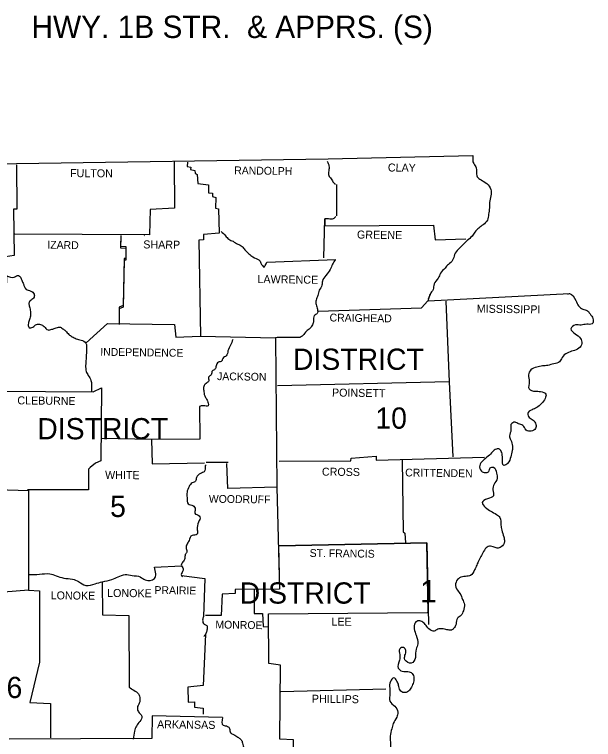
# Model space of a CAD drawing. Extents: x 155 to 3386, y 68 to 2138.
# Drawn here: x 2999.8 to 3303.9, y 1654.1 to 2035 of the extents above; entities that cross this region are included whole.
import ezdxf

# ---------------------------------------------------------------- set-up
doc = ezdxf.new("R2010")
doc.units = 0
for name, color, linetype in [('1', 7, 'Continuous'), ('2', 7, 'Continuous'), ('3', 7, 'Continuous'), ('R_Border', 7, 'Continuous'), ('S_MISC_BOUNDARY', 7, 'Continuous')]:
    doc.layers.add(name, color=color, linetype=linetype)

msp = doc.modelspace()

# ---------------------------------------------------------------- linework, layer by layer
at = {"layer": '1'}
for p, q in [((3216.98, 1884.51), (3218.15, 1888.13)), ((3217.27, 1885.68), (3218.45, 1888.52)), ((3100.35, 1799.78), (3112, 1799.78))]:
    msp.add_line(p, q, dxfattribs=at)
for points in [[(2703.71, 1956.42), (2861.92, 1956.32), (3000.75, 1956.61), (3164.54, 1959.16), (3240.46, 1960.92)], [(3083.62, 1957.49), (3083.82, 1933.23), (3071.1, 1932.55), (3070.71, 1919.24), (2999.97, 1919.63)], [(3090.67, 1957.4), (3090.37, 1955.05), (3092.33, 1954.76), (3092.23, 1953.58), (3094.48, 1953.09), (3094.68, 1951.53), (3095.75, 1950.84), (3096.05, 1946.15), (3101.63, 1945.56), (3101.63, 1941.35), (3103.68, 1941.06), (3103.68, 1939.39), (3105.44, 1938.9), (3105.34, 1933.23), (3106.91, 1932.94), (3107.3, 1920.12), (3098.98, 1919.34), (3099.08, 1916.6), (3096.54, 1916.5), (3097.42, 1866.01), (3136.85, 1865.13), (3137.53, 1786.66), (3111.8, 1785.98), (3111.31, 1799.19)], [(3000.75, 1956.03), (3000.95, 1932.74), (2999.28, 1932.64), (2999.58, 1908.28), (2992.73, 1907.3), (2993.32, 1900.75), (2995.66, 1897.71), (2995.47, 1889.98), (2982.16, 1889.5), (2981.67, 1877.56), (2969.54, 1877.17), (2968.95, 1862.69), (2969.64, 1861.51), (2969.93, 1838.42), (2990.87, 1837.05), (2990.58, 1785.49), (3007.21, 1785), (3007.21, 1732.56), (2994.1, 1731.58), (2993.12, 1720.04), (2971.11, 1719.94)], [(3168.84, 1945.66), (3168.84, 1929.12)], [(3162.19, 1907.11), (3162.68, 1927.56), (3162.68, 1923.94), (3219.91, 1924.23), (3220.7, 1916.6), (3236.84, 1917.18)], [(3055.64, 1918.95), (3055.44, 1913.27), (3058.18, 1913.07), (3058.28, 1906.81), (3057.3, 1906.81), (3056.91, 1882.16), (3054.66, 1881.18), (3054.66, 1872.96)], [(3055.64, 1918.06), (3055.44, 1912.39), (3058.18, 1912.19), (3058.28, 1905.93), (3057.3, 1905.93), (3056.91, 1881.28), (3054.66, 1880.3), (3054.66, 1872.08)], [(3067.87, 1918.75), (3067.97, 1918.85)], [(3132.25, 1904.95), (3168.55, 1906.23)], [(3216.98, 1884.51), (3291.24, 1888.32)], [(3159.25, 1879.12), (3213.55, 1880.89), (3216.78, 1884.6)], [(3226.37, 1884.41), (3228.04, 1842.04), (3229.99, 1802.61)], [(3037.44, 1862.49), (3048.6, 1872.57), (3083.82, 1872.08), (3084.5, 1865.52), (3097.32, 1866.01)], [(3149.67, 1865.33), (3137.73, 1865.33), (3136.85, 1865.13)], [(3228.04, 1842.04), (3137.92, 1839.99)], [(2990.87, 1837.05), (3041.16, 1836.76), (3045.46, 1838.81), (3045.17, 1800.56), (3042.24, 1799.29), (3039.59, 1797.04), (3038.71, 1796.16), (3038.62, 1785.2), (3006.62, 1785.2)], [(3096.93, 1829.03), (3097.12, 1811.81), (3071.69, 1811.71), (3045.56, 1812.2)], [(3071.69, 1811.71), (3072.08, 1798.89), (3099.57, 1799.38)], [(3138.71, 1800.36), (3176.47, 1800.56), (3176.57, 1801.93), (3189.68, 1802.91), (3189.68, 1800.85), (3246.63, 1802.42)], [(3100.35, 1798.11), (3099.86, 1798.01)], [(3203.38, 1800.85), (3203.87, 1763.18), (3204.75, 1762.6), (3205.04, 1757.51)], [(3137.53, 1786.66), (3139, 1733.05), (3115.71, 1732.95), (3115.62, 1730.8), (3108.87, 1730.41), (3108.28, 1719.25), (3100.06, 1719.25)], [(3138.71, 1755.85), (3216.39, 1757.41)], [(3216.39, 1757.41), (3217.18, 1714.56)], [(3073.25, 1744.69), (3087.44, 1745.38)], [(3045.86, 1737.06), (3046.05, 1719.55), (3059.85, 1719.25), (3059.95, 1681.68)], [(3087.44, 1740.29), (3099.67, 1738.72), (3098.98, 1718.76)], [(3007.21, 1732.56), (3012.88, 1732.17), (3012.98, 1694.79), (3007.89, 1673.56), (3018.75, 1673.07), (3018.66, 1655.07)], [(3125.69, 1732.46), (3125.6, 1720.33), (3130.1, 1720.33), (3130.29, 1713.58), (3133.13, 1713.28)], [(3138.71, 1633.54), (3146.34, 1634.03), (3146.24, 1653.9), (3139.1, 1654.38), (3139.49, 1693.23), (3133.33, 1694.11), (3133.13, 1720.23), (3216.59, 1720.82)], [(3100.06, 1709.37), (3098.89, 1682.56), (3090.86, 1681.68), (3091.06, 1673.76), (3094.29, 1673.85), (3094.39, 1671.11), (3098.79, 1670.63), (3098.89, 1667.4)], [(3139.69, 1679.43), (3194.87, 1680.8)], [(3109.06, 1665.64), (3072.08, 1666.61), (3071.88, 1654.58), (2997.03, 1654.29)]]:
    msp.add_lwpolyline(points, dxfattribs=at)
for points in [[(3164.05, 1957.89), (3164.93, 1955.44), (3164.83, 1952.8), (3164.83, 1950.35), (3166.1, 1948.69), (3167.37, 1946.63), (3168.35, 1945.75)], [(3240.46, 1960.92), (3240.95, 1956.61), (3242.32, 1954.36), (3242.52, 1950.25), (3244.18, 1948.49), (3247.02, 1946.73), (3249.56, 1943.89), (3250.15, 1940.57), (3249.36, 1937.14), (3249.17, 1933.33), (3248.78, 1930), (3248.19, 1926.97), (3245.84, 1924.52), (3243.59, 1922.76), (3241.54, 1920.71), (3240.07, 1918.55), (3237.53, 1916.21), (3234.98, 1913.76), (3232.93, 1911.61), (3230.87, 1908.87), (3229.89, 1905.83), (3227.64, 1903.68), (3225.88, 1901.73), (3223.53, 1899.08), (3222.36, 1896.44), (3220.11, 1893.41), (3219.62, 1890.47), (3218.15, 1888.13), (3218.06, 1887.73)], [(3168.45, 1928.83), (3167.18, 1927.56), (3164.73, 1927.56), (3162.68, 1927.56)], [(3108.38, 1921), (3110.53, 1918.75), (3112.39, 1916.89), (3114.54, 1915.81), (3117.08, 1914.35), (3119.33, 1913.17), (3120.8, 1911.31), (3122.86, 1909.26), (3124.91, 1907.6), (3128.14, 1906.03), (3129.22, 1904.37), (3130.68, 1902.31), (3132.25, 1904.95)], [(3168.25, 1906.13), (3166.79, 1903.78), (3165.61, 1901.04), (3163.26, 1897.91), (3161.5, 1894.88), (3161.21, 1892.82), (3159.84, 1890.08), (3159.06, 1887.34), (3158.18, 1884.99), (3158.18, 1882.55), (3158.86, 1880.1), (3158.67, 1877.85), (3157.2, 1876.78), (3156.81, 1873.94), (3156.22, 1871.98), (3154.95, 1870.03), (3153.09, 1868.56), (3151.13, 1866.31), (3149.67, 1865.33)], [(2995.66, 1897.71), (2999.58, 1897.03), (3001.93, 1897.91), (3003.59, 1895.37), (3004.47, 1893.41), (3005.94, 1890.57), (3008.29, 1889.69), (3010.05, 1888.13), (3010.05, 1886.46), (3008.48, 1884.9), (3007.31, 1883.33), (3007.7, 1881.47), (3008.09, 1878.93), (3008.09, 1876.48), (3007.5, 1874.23), (3007.01, 1872.18), (3007.5, 1870.42), (3009.36, 1870.71), (3011.32, 1872.18), (3013.37, 1872.18), (3015.33, 1871.1), (3017.38, 1869.24), (3019.44, 1869.63), (3021.1, 1870.12), (3023.45, 1870.81), (3025.11, 1869.93), (3026.58, 1868.75), (3028.34, 1866.89), (3030.01, 1865.72), (3032.16, 1864.64), (3034.8, 1863.96), (3037.25, 1862.3), (3037.64, 1859.46), (3037.54, 1857.01), (3037.34, 1853.98), (3037.15, 1850.65), (3037.44, 1847.42), (3038.52, 1845.27), (3039.89, 1842.73), (3040.28, 1840.38), (3040.18, 1836.66)], [(3290.16, 1888.22), (3291.24, 1888.32), (3294.57, 1884.8), (3296.03, 1881.86), (3298.19, 1880.2), (3300.63, 1879.32), (3302.49, 1877.07), (3303.76, 1874.62), (3303.08, 1872.47), (3300.34, 1872.28), (3297.31, 1871.79), (3294.37, 1871.88), (3292.02, 1869.93), (3294.18, 1867.29), (3297.01, 1864.84), (3297.8, 1862.2), (3296.23, 1859.65), (3293.1, 1858.28), (3290.07, 1857.11), (3287.33, 1854.76), (3286.05, 1852.51), (3283.02, 1851.53), (3279.89, 1850.65), (3277.15, 1850.36), (3274.02, 1849.77), (3270.99, 1848.3), (3269.72, 1845.76), (3270.11, 1842.14), (3270.01, 1838.32), (3273.24, 1837.05), (3276.08, 1836.95), (3278.81, 1835.49), (3278.52, 1833.33), (3276.47, 1830.6), (3274.02, 1828.44), (3271.57, 1827.37), (3269.32, 1825.31), (3270.11, 1823.26), (3272.16, 1821.89), (3273.63, 1819.64), (3273.43, 1817.58), (3271.09, 1816.11), (3268.54, 1816.7), (3266.68, 1819.15), (3264.53, 1819.93), (3262.67, 1820.81), (3260.52, 1819.54), (3260.52, 1816.7), (3259.74, 1813.67), (3260.42, 1811.42), (3261.3, 1808.29), (3261.2, 1805.94), (3260.42, 1802.61), (3258.76, 1799.19), (3256.8, 1798.11), (3256.02, 1801.83), (3255.63, 1804.86), (3254.45, 1806.62), (3252.89, 1806.72), (3250.83, 1805.25), (3248.58, 1803), (3245.74, 1800.56), (3244.08, 1798.11), (3244.96, 1795.08), (3247.11, 1794.3), (3248.78, 1794.88), (3249.66, 1796.84), (3251.32, 1797.13), (3252.89, 1794.1)], [(3114.44, 1864.25), (3113.27, 1861.22), (3111.9, 1858.28), (3111.02, 1855.74), (3109.16, 1854.27), (3108.57, 1852.9), (3106.91, 1852.32), (3105.64, 1850.36), (3105.05, 1848.6), (3103.68, 1847.82), (3103, 1845.66), (3101.72, 1844.49), (3101.82, 1842.53), (3100.35, 1841.16), (3099.18, 1839.6), (3099.18, 1837.44), (3099.67, 1834.61), (3100.65, 1832.94), (3101.53, 1830.79), (3101.43, 1829.42), (3098.98, 1829.42), (3096.93, 1829.03)], [(3099.86, 1798.01), (3099.37, 1794.79), (3097.52, 1793.91), (3095.36, 1791.75), (3094.87, 1789.8), (3093.11, 1789.01), (3091.45, 1786.96), (3090.37, 1784.12), (3090.37, 1781.19), (3091.06, 1777.86), (3093.5, 1776.98), (3094.68, 1775.02), (3094.48, 1772.97), (3096.83, 1771.6), (3097.22, 1770.42), (3096.83, 1769.15), (3095.75, 1765.53), (3095.85, 1763.09), (3095.66, 1762.01), (3093.02, 1761.32), (3091.45, 1758.68), (3090.37, 1756.82), (3089.98, 1754.38), (3090.28, 1752.62), (3089.49, 1751.25), (3089.2, 1749.19), (3088.22, 1747.43), (3087.34, 1745.77), (3088.32, 1743.81), (3088.03, 1742.44), (3087.44, 1740.29), (3087.93, 1739.6)], [(3252.89, 1794.1), (3253.28, 1791.26), (3251.62, 1788.23), (3251.03, 1785.2), (3251.32, 1782.16), (3248.19, 1780.5), (3245.45, 1778.54), (3247.02, 1776.2), (3249.95, 1774.04), (3252.89, 1772.38), (3254.75, 1770.72), (3255.24, 1766.71), (3255.72, 1764.16), (3256.7, 1760.64), (3257.09, 1758.19), (3255.33, 1755.26), (3253.28, 1754.67), (3251.13, 1755.36), (3248.58, 1755.55), (3246.53, 1753.59), (3245.06, 1750.86), (3243.59, 1748.12), (3242.52, 1745.77), (3241.44, 1743.22), (3239.29, 1740.29), (3236.65, 1739.8), (3233.51, 1739.02), (3231.66, 1736.86), (3231.95, 1733.24), (3233.71, 1730.8), (3235.08, 1727.76), (3236.06, 1725.12), (3235.57, 1721.8), (3234.2, 1719.35), (3232.44, 1717.88), (3231.66, 1714.75), (3230.38, 1712.4), (3229.21, 1711.62), (3226.86, 1711.82), (3224.32, 1712.31), (3222.16, 1712.11), (3220.11, 1711.03), (3218.06, 1711.72), (3215.9, 1714.07), (3214.14, 1715.83), (3212.19, 1716.51), (3210.13, 1715.44), (3209.74, 1712.21), (3210.72, 1708.88), (3211.6, 1704.38), (3210.72, 1701.64), (3210.42, 1697.14)], [(3007.4, 1740.78), (3012.88, 1740.97), (3018.26, 1741.17), (3021.69, 1740.19), (3025.6, 1738.92), (3030.2, 1738.33), (3033.43, 1737.06), (3037.25, 1735.1), (3042.14, 1735.98), (3045.95, 1736.96), (3050.94, 1738.23), (3054.17, 1739.6), (3057.89, 1740.78), (3061.61, 1740.29), (3065.82, 1739.51), (3068.46, 1737.94), (3073.25, 1738.63), (3073.25, 1744.69)], [(3098.98, 1718.76), (3098.59, 1716.81), (3099.37, 1714.75), (3100.74, 1714.07), (3100.94, 1712.11), (3100.45, 1710.15), (3100.06, 1709.37), (3099.18, 1708.2)], [(3210.42, 1697.14), (3208.17, 1694.3), (3204.85, 1696.06), (3204.85, 1698.41), (3205.34, 1700.86), (3204.16, 1702.42), (3202.11, 1701.74), (3202.11, 1698.71), (3201.91, 1695.77), (3201.32, 1691.56), (3202.69, 1690.29), (3205.83, 1689.9), (3208.08, 1689.31), (3209.45, 1687.06), (3209.35, 1684.32), (3208.27, 1681.68), (3206.71, 1679.53), (3204.26, 1678.75), (3202.3, 1680.02), (3201.52, 1682.56), (3200.64, 1684.81), (3198.98, 1686.48), (3197.22, 1684.62), (3196.82, 1681.19), (3196.92, 1678.26), (3196.92, 1674.25), (3199.47, 1671.6), (3201.03, 1668.57), (3200.54, 1665.83), (3198.68, 1662.6), (3197.9, 1659.77), (3197.12, 1655.95), (3197.22, 1651.74), (3196.53, 1647.63), (3195.16, 1644.89), (3192.62, 1642.64), (3190.95, 1641.18), (3189.58, 1639.71), (3188.9, 1636.77), (3188.41, 1634.72), (3186.55, 1632.27), (3185.08, 1632.08), (3183.91, 1633.05), (3183.52, 1634.72), (3183.52, 1636.38), (3182.74, 1638.04), (3180.29, 1638.73), (3178.33, 1638.63), (3177.45, 1637.26), (3178.72, 1633.45), (3179.21, 1631), (3178.53, 1627.67), (3178.92, 1627.28), (3175.4, 1625.42), (3172.56, 1625.13), (3170.21, 1624.44), (3167.96, 1622.98), (3166.88, 1620.82), (3165.32, 1619.06), (3163.95, 1617.4), (3162.09, 1616.62), (3160.04, 1617.01), (3157.3, 1617.3), (3155.73, 1615.35), (3156.22, 1612.51), (3158.08, 1610.85), (3160.82, 1610.06), (3163.66, 1610.26), (3166.4, 1610.55), (3168.94, 1609.18), (3168.45, 1606.54), (3166, 1605.27), (3162.38, 1604.88), (3159.45, 1605.17), (3155.93, 1604.39), (3154.17, 1602.14), (3155.14, 1598.71), (3158.96, 1597.34), (3160.72, 1594.11), (3160.82, 1591.08), (3159.55, 1587.07), (3157.79, 1585.21), (3154.36, 1584.43), (3151.72, 1583.94), (3151.33, 1579.44), (3150.15, 1577.19), (3148.1, 1576.5), (3145.16, 1577.97), (3143.4, 1578.66), (3141.25, 1579.63), (3138.51, 1581.3), (3136.46, 1581), (3137.04, 1576.7), (3137.24, 1576.5), (3139.59, 1573.27), (3141.94, 1570.73), (3143.01, 1567.7)], [(3059.95, 1681.68), (3062.39, 1680.02), (3064.93, 1678.06), (3065.62, 1675.42), (3065.42, 1673.56), (3064.64, 1672), (3064.45, 1669.55), (3065.62, 1667.79), (3066.7, 1666.32), (3065.62, 1663.68), (3063.76, 1661.23), (3062.78, 1658.49), (3062.1, 1654.38)], [(3109.06, 1665.64), (3109.35, 1661.62), (3111.7, 1661.04), (3112.68, 1659.96), (3113.17, 1657.71), (3114.83, 1656.73), (3117.08, 1655.36), (3118.45, 1654.38), (3119.43, 1652.82), (3120.02, 1650.27), (3121.58, 1648.61), (3123.74, 1647.83), (3125.3, 1645.97), (3126.28, 1643.33), (3127.85, 1642.15), (3129.41, 1640.1), (3130.19, 1639.22), (3131.56, 1636.87), (3132.93, 1635.7), (3133.91, 1635.01), (3135.48, 1634.52), (3137.43, 1633.25), (3138.71, 1631.29), (3138.71, 1629.83), (3138.22, 1627.58), (3137.83, 1625.23), (3137.63, 1622.59), (3137.43, 1620.24), (3138.32, 1618.28), (3137.83, 1615.35), (3136.85, 1613.78), (3136.75, 1611.63), (3136.46, 1608.4), (3136.07, 1606.54), (3135.18, 1603.51), (3133.91, 1601.94)]]:
    msp.add_spline(points, degree=3, dxfattribs=at)
at = {"layer": 'S_MISC_BOUNDARY'}
for p, q in [((3216.39, 1757.41), (3138.71, 1755.85)), ((3217.06, 1720.83), (3216.39, 1757.41)), ((3133.13, 1720.23), (3216.59, 1720.82)), ((3133.18, 1713.28), (3133.13, 1720.23))]:
    msp.add_line(p, q, dxfattribs=at)
for points in [[(3138.38, 1755.84), (3139, 1733.05), (3125.69, 1732.99)], [(3138.71, 1755.85), (3138.38, 1755.84)], [(3125.69, 1732.99), (3125.69, 1732.46)], [(3125.69, 1732.46), (3125.6, 1720.33), (3130.1, 1720.33), (3130.29, 1713.58), (3133.13, 1713.28)], [(3216.59, 1720.82), (3217.06, 1720.83)], [(3133.13, 1713.28), (3133.18, 1713.28)]]:
    msp.add_lwpolyline(points, dxfattribs=at)

# ---------------------------------------------------------------- texts
at = {"layer": '1'}
msp.add_text('1', height=11.74, dxfattribs=at).set_placement((3212.77, 1726.2))
at = {"layer": '2'}
for s, height, rotation, p in [('FULTON', 4.206, 359.4996, (3028.93, 1949.57)), ('RANDOLPH', 4.109, 359.2583, (3115.13, 1951.04)), ('CLAY', 4.206, 359.2258, (3195.85, 1952.5)), ('GREENE', 4.207, 359.2361, (3179.6, 1917.28)), ('IZARD', 4.108, 358.9258, (3016.99, 1912)), ('SHARP', 4.206, 359.3905, (3067.38, 1912.1)), ('LAWRENCE', 4.207, 359.2678, (3127.36, 1893.9)), ('MISSISSIPPI', 4.2062, 359.3097, (3242.52, 1878.34)), ('CRAIGHEAD', 4.109, 359.1159, (3165.22, 1873.74)), ('INDEPENDENCE', 4.1081, 359.2187, (3044.78, 1855.74)), ('JACKSON', 4.108, 359.1352, (3106.13, 1842.92)), ('POINSETT', 4.206, 359.1987, (3166.49, 1834.31)), ('CLEBURNE', 4.206, 359.2535, (3001.24, 1830.2)), ('WHITE', 4.207, 359.3139, (3047.32, 1791.07)), ('CROSS', 4.206, 359.3839, (3161.21, 1792.73)), ('CRITTENDEN', 4.109, 359.213, (3204.94, 1792.34)), ('WOODRUFF', 4.108, 359.2748, (3101.82, 1778.54)), ('ST. FRANCIS', 4.1081, 359.2216, (3154.75, 1750.07)), ('LONOKE', 4.207, 359.4974, (3048.4, 1729.04)), ('PRAIRIE', 4.109, 359.2116, (3073.25, 1730.6)), ('LONOKE', 4.207, 359.4974, (3018.75, 1727.76)), ('LEE', 4.207, 359.4327, (3166.2, 1713.97)), ('MONROE', 4.108, 359.0331, (3105.25, 1712.5)), ('PHILLIPS', 4.206, 359.3179, (3155.93, 1673.46)), ('ARKANSAS', 4.206, 359.2678, (3074.62, 1660.06))]:
    msp.add_text(s, height=height, rotation=rotation, dxfattribs=at).set_placement(p)
at = {"layer": '3'}
for s, height, p in [('DISTRICT', 11.154, (3146, 1848.31)), ('10', 11.154, (3189.29, 1817.39)), ('DISTRICT', 11.154, (3011.71, 1811.81)), ('5', 11.15, (3049.97, 1771.01)), ('DISTRICT', 11.154, (3118.06, 1725.51)), ('DISTRICT 6', 11.154, (2922.67, 1675.91))]:
    msp.add_text(s, height=height, dxfattribs=at).set_placement(p)
at = {"layer": 'R_Border'}
msp.add_text('HWY. 1B STR.  & APPRS. (S)', height=11.724, dxfattribs=at).set_placement((3008.67, 2022.61))

doc.saveas('drawing.dxf')
